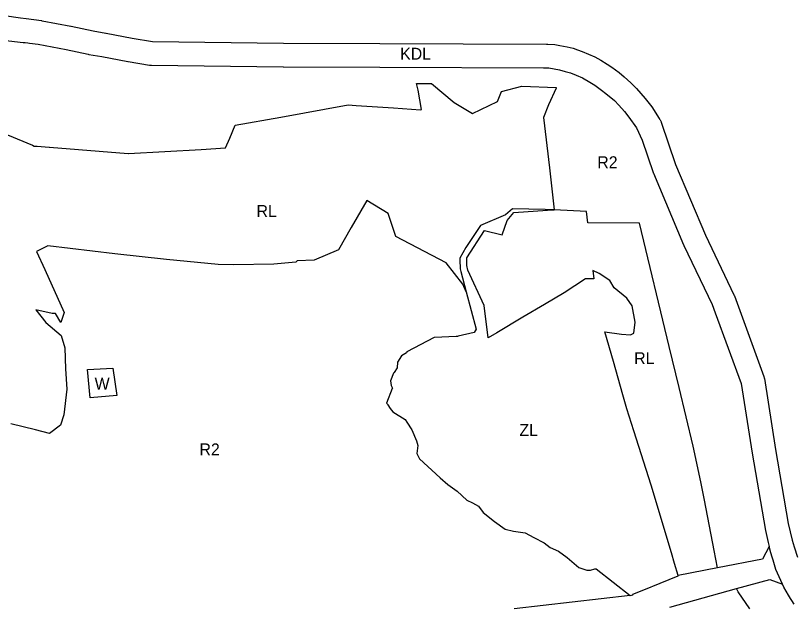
# Model space of a CAD drawing. Extents: x 7413438 to 7416393, y 5541665 to 5544118.
# Drawn here: x 7414455.4 to 7414848.9, y 5543282 to 5543578.9 of the extents above; entities that cross this region are included whole.
import ezdxf

# ---------------------------------------------------------------- set-up
doc = ezdxf.new("R2010")
doc.units = 0
doc.layers.add('linie_rozgraniczajace', color=7, linetype='Continuous')
doc.layers.add('oznaczenia_przeznaczen', color=7, linetype='Continuous')

msp = doc.modelspace()

# ---------------------------------------------------------------- linework, layer by layer
at = {"layer": 'linie_rozgraniczajace'}
for p, q in [((7414449.82, 5543578.9), (7414457.83, 5543577.78)), ((7414457.83, 5543577.78), (7414460.76, 5543577.39)), ((7414460.76, 5543577.39), (7414468.45, 5543576.35)), ((7414468.45, 5543576.35), (7414468.59, 5543576.33)), ((7414468.59, 5543576.33), (7414468.77, 5543576.3)), ((7414468.77, 5543576.3), (7414483.31, 5543573.58)), ((7414483.31, 5543573.58), (7414483.49, 5543573.54)), ((7414483.49, 5543573.54), (7414494.55, 5543571.12)), ((7414425.24, 5543568.95), (7414459.26, 5543565.39)), ((7414494.55, 5543571.12), (7414500.92, 5543570.09)), ((7414500.92, 5543570.09), (7414501.08, 5543570.06)), ((7414501.08, 5543570.06), (7414514.21, 5543567.57)), ((7414514.21, 5543567.57), (7414524.63, 5543565.84)), ((7414459.26, 5543565.39), (7414460.16, 5543565.34)), ((7414460.16, 5543565.34), (7414461.6, 5543565.15)), ((7414461.6, 5543565.15), (7414462.45, 5543565.04)), ((7414462.45, 5543565.04), (7414466.72, 5543564.48)), ((7414466.72, 5543564.48), (7414481.01, 5543561.8)), ((7414524.63, 5543565.84), (7414590.76, 5543564.98)), ((7414590.76, 5543564.98), (7414639.46, 5543564.84)), ((7414639.46, 5543564.84), (7414639.46, 5543564.84)), ((7414639.46, 5543564.84), (7414723.68, 5543564.55)), ((7414723.68, 5543564.55), (7414723.81, 5543564.54)), ((7414723.81, 5543564.54), (7414724.2, 5543564.52)), ((7414724.2, 5543564.52), (7414724.27, 5543564.51)), ((7414724.27, 5543564.51), (7414727.91, 5543564.31)), ((7414727.91, 5543564.31), (7414730.37, 5543563.77)), ((7414730.37, 5543563.77), (7414734.05, 5543563.08)), ((7414481.01, 5543561.8), (7414492.14, 5543559.36)), ((7414492.14, 5543559.36), (7414492.47, 5543559.3)), ((7414734.05, 5543563.08), (7414737.1, 5543562.37)), ((7414737.1, 5543562.37), (7414739.31, 5543561.63)), ((7414739.31, 5543561.63), (7414741.6, 5543560.76)), ((7414741.6, 5543560.76), (7414744.86, 5543559.48)), ((7414744.86, 5543559.48), (7414748, 5543558.06)), ((7414492.47, 5543559.3), (7414498.92, 5543558.26)), ((7414498.92, 5543558.26), (7414512.05, 5543555.76)), ((7414512.05, 5543555.76), (7414512.19, 5543555.74)), ((7414512.19, 5543555.74), (7414523.12, 5543553.93)), ((7414748, 5543558.06), (7414751.14, 5543556.39)), ((7414751.14, 5543556.39), (7414754.31, 5543554.34)), ((7414523.12, 5543553.93), (7414523.16, 5543553.92)), ((7414523.16, 5543553.92), (7414523.19, 5543553.92)), ((7414523.19, 5543553.92), (7414523.55, 5543553.87)), ((7414523.55, 5543553.87), (7414523.95, 5543553.85)), ((7414523.95, 5543553.85), (7414524.02, 5543553.85)), ((7414524.02, 5543553.85), (7414590.64, 5543552.98)), ((7414590.64, 5543552.98), (7414590.7, 5543552.98)), ((7414590.7, 5543552.98), (7414639.43, 5543552.84)), ((7414639.43, 5543552.84), (7414722.1, 5543552.55)), ((7414722.1, 5543552.55), (7414722.11, 5543552.55)), ((7414722.11, 5543552.55), (7414722.6, 5543552.55)), ((7414722.6, 5543552.55), (7414722.63, 5543552.54)), ((7414722.63, 5543552.54), (7414724.79, 5543552.5)), ((7414724.79, 5543552.5), (7414727.51, 5543551.97)), ((7414727.51, 5543551.97), (7414730.16, 5543551.56)), ((7414730.16, 5543551.56), (7414733.08, 5543550.72)), ((7414754.31, 5543554.34), (7414756.55, 5543552.89)), ((7414756.55, 5543552.89), (7414760.26, 5543550.09)), ((7414733.08, 5543550.72), (7414735.81, 5543549.93)), ((7414735.81, 5543549.93), (7414738.61, 5543548.82)), ((7414738.61, 5543548.82), (7414741.75, 5543547.41)), ((7414760.26, 5543550.09), (7414762.85, 5543547.94)), ((7414762.85, 5543547.94), (7414766.18, 5543545)), ((7414658.18, 5543543.92), (7414657.91, 5543544.56)), ((7414657.91, 5543544.56), (7414665.54, 5543544.53)), ((7414658.71, 5543541.16), (7414658.18, 5543543.92)), ((7414665.54, 5543544.53), (7414676.92, 5543534.99)), ((7414741.75, 5543547.41), (7414745.5, 5543545.31)), ((7414745.5, 5543545.31), (7414748.06, 5543543.75)), ((7414748.06, 5543543.75), (7414751.44, 5543541.25)), ((7414766.18, 5543545), (7414769.12, 5543542.1)), ((7414660.52, 5543531.53), (7414658.71, 5543541.16)), ((7414698.91, 5543535.45), (7414700.84, 5543540.53)), ((7414700.84, 5543540.53), (7414711.16, 5543543.24)), ((7414711.16, 5543543.24), (7414728.58, 5543542.52)), ((7414728.53, 5543542.16), (7414724.56, 5543533.83)), ((7414728.58, 5543542.52), (7414728.53, 5543542.16)), ((7414751.44, 5543541.25), (7414753.56, 5543539.61)), ((7414769.12, 5543542.1), (7414773.44, 5543536.95)), ((7414753.56, 5543539.61), (7414757.94, 5543536)), ((7414757.94, 5543536), (7414760.22, 5543533.59)), ((7414773.44, 5543536.95), (7414776.88, 5543532.79)), ((7414589.39, 5543527.67), (7414623.38, 5543533.78)), ((7414623.38, 5543533.78), (7414627.44, 5543533.51)), ((7414627.44, 5543533.51), (7414646.34, 5543532.24)), ((7414646.34, 5543532.24), (7414659.92, 5543531.33)), ((7414676.92, 5543534.99), (7414686.15, 5543529.51)), ((7414686.15, 5543529.51), (7414698.91, 5543535.45)), ((7414724.56, 5543533.83), (7414722.08, 5543527.36)), ((7414760.22, 5543533.59), (7414762.98, 5543530.49)), ((7414776.88, 5543532.79), (7414780.59, 5543526.86)), ((7414659.92, 5543531.33), (7414660.52, 5543531.53)), ((7414762.98, 5543530.49), (7414765.28, 5543527.63)), ((7414566.41, 5543523.54), (7414589.39, 5543527.67)), ((7414722.08, 5543527.36), (7414725.09, 5543502)), ((7414765.28, 5543527.63), (7414769.14, 5543522.19)), ((7414780.59, 5543526.86), (7414780.64, 5543526.8)), ((7414780.64, 5543526.8), (7414780.79, 5543526.6)), ((7414780.79, 5543526.6), (7414781.01, 5543526.28)), ((7414781.01, 5543526.28), (7414781.21, 5543525.94)), ((7414781.21, 5543525.94), (7414781.38, 5543525.59)), ((7414781.38, 5543525.59), (7414781.54, 5543525.23)), ((7414781.54, 5543525.23), (7414781.62, 5543524.99)), ((7414781.62, 5543524.99), (7414788.78, 5543503.77)), ((7414563.55, 5543516.96), (7414566.41, 5543523.54)), ((7414769.14, 5543522.19), (7414772.02, 5543515.92)), ((7414451.36, 5543518.66), (7414463.89, 5543513.39)), ((7414561.39, 5543512.03), (7414563.55, 5543516.96)), ((7414463.89, 5543513.39), (7414464.79, 5543513.01)), ((7414464.79, 5543513.01), (7414466.24, 5543512.9)), ((7414466.24, 5543512.9), (7414472.32, 5543512.41)), ((7414472.32, 5543512.41), (7414472.58, 5543512.39)), ((7414472.58, 5543512.39), (7414512.33, 5543509.21)), ((7414772.02, 5543515.92), (7414777.48, 5543499.73)), ((7414512.33, 5543509.21), (7414512.41, 5543509.2)), ((7414512.41, 5543509.2), (7414549.07, 5543511.32)), ((7414549.07, 5543511.32), (7414561.39, 5543512.03)), ((7414725.09, 5543502), (7414727.48, 5543480.86)), ((7414788.78, 5543503.77), (7414803.87, 5543467.92)), ((7414777.48, 5543499.73), (7414777.56, 5543499.49)), ((7414777.56, 5543499.49), (7414777.63, 5543499.32)), ((7414777.63, 5543499.32), (7414792.87, 5543463.13)), ((7414632.89, 5543485.46), (7414625, 5543471.83)), ((7414643.7, 5543479.01), (7414632.89, 5543485.46)), ((7414706.45, 5543481.38), (7414702.82, 5543478.25)), ((7414723.01, 5543480.97), (7414706.45, 5543481.38)), ((7414727.48, 5543480.86), (7414723.01, 5543480.97)), ((7414724.04, 5543480.62), (7414727.48, 5543480.86)), ((7414743.75, 5543479.89), (7414727.48, 5543480.86)), ((7414647.46, 5543467.36), (7414643.7, 5543479.01)), ((7414702.82, 5543478.25), (7414690.34, 5543472.8)), ((7414703.79, 5543475.36), (7414707.18, 5543479.43)), ((7414707.18, 5543479.43), (7414724.04, 5543480.62)), ((7414744.47, 5543474.26), (7414743.75, 5543479.89)), ((7414690.34, 5543472.8), (7414682.82, 5543461.74)), ((7414701.15, 5543468.2), (7414703.79, 5543475.36)), ((7414770.58, 5543474.13), (7414744.47, 5543474.26)), ((7414785.56, 5543411.81), (7414770.58, 5543474.13)), ((7414625, 5543471.83), (7414618.54, 5543460.64)), ((7414683.33, 5543456.51), (7414692.25, 5543470.39)), ((7414692.25, 5543470.39), (7414701.15, 5543468.2)), ((7414672.96, 5543454.07), (7414647.46, 5543467.36)), ((7414803.87, 5543467.92), (7414818.27, 5543437.93)), ((7414471.72, 5543462.53), (7414466.03, 5543459.67)), ((7414505.47, 5543458.65), (7414471.72, 5543462.53)), ((7414682.82, 5543461.74), (7414679.75, 5543456.32)), ((7414792.87, 5543463.13), (7414792.96, 5543462.94)), ((7414792.96, 5543462.94), (7414792.99, 5543462.86)), ((7414792.99, 5543462.86), (7414807.33, 5543433)), ((7414466.03, 5543459.67), (7414470.1, 5543450.65)), ((7414531.7, 5543455.77), (7414505.47, 5543458.65)), ((7414618.54, 5543460.64), (7414606.28, 5543455.3)), ((7414557.79, 5543453.24), (7414531.7, 5543455.77)), ((7414565.47, 5543453.08), (7414557.79, 5543453.24)), ((7414585.8, 5543453.35), (7414565.47, 5543453.08)), ((7414596.91, 5543454.41), (7414585.8, 5543453.35)), ((7414597.69, 5543455.08), (7414596.91, 5543454.41)), ((7414606.28, 5543455.3), (7414597.69, 5543455.08)), ((7414681.33, 5543443.17), (7414672.96, 5543454.07)), ((7414679.75, 5543456.32), (7414679.81, 5543455.56)), ((7414679.81, 5543455.56), (7414679.93, 5543451.07)), ((7414683.36, 5543452.73), (7414683.33, 5543456.51)), ((7414470.1, 5543450.65), (7414479.91, 5543428.89)), ((7414679.93, 5543451.07), (7414680.32, 5543449.59)), ((7414680.32, 5543449.59), (7414683.02, 5543439.44)), ((7414683.94, 5543450.29), (7414683.36, 5543452.73)), ((7414692.07, 5543432.48), (7414683.94, 5543450.29)), ((7414747.1, 5543450.22), (7414747.07, 5543450.17)), ((7414747.07, 5543450.17), (7414747.52, 5543445.95)), ((7414750.24, 5543448.56), (7414747.1, 5543450.22)), ((7414743.4, 5543446.01), (7414732.49, 5543438.88)), ((7414747.52, 5543445.95), (7414743.4, 5543446.01)), ((7414755.65, 5543445.12), (7414750.24, 5543448.56)), ((7414683, 5543439.43), (7414681.33, 5543443.17)), ((7414757.73, 5543441.45), (7414755.65, 5543445.12)), ((7414764.18, 5543436.23), (7414757.73, 5543441.45)), ((7414683.02, 5543439.44), (7414683, 5543439.43)), ((7414683, 5543439.43), (7414683.04, 5543439.35)), ((7414683.04, 5543439.35), (7414688.07, 5543420.51)), ((7414732.49, 5543438.88), (7414722.55, 5543432.98)), ((7414818.27, 5543437.93), (7414818.31, 5543437.85)), ((7414818.31, 5543437.85), (7414818.46, 5543437.49)), ((7414818.46, 5543437.49), (7414818.5, 5543437.39)), ((7414818.5, 5543437.39), (7414818.54, 5543437.29)), ((7414766.92, 5543432.25), (7414764.18, 5543436.23)), ((7414818.54, 5543437.29), (7414833.39, 5543396.69)), ((7414473.79, 5543428.36), (7414465.7, 5543430.34)), ((7414465.7, 5543430.34), (7414470.72, 5543423.93)), ((7414694.23, 5543416.15), (7414692.07, 5543432.48)), ((7414722.55, 5543432.98), (7414711.68, 5543426.52)), ((7414768.43, 5543424.04), (7414766.92, 5543432.25)), ((7414807.33, 5543433), (7414808.88, 5543428.75)), ((7414475.54, 5543428.51), (7414473.79, 5543428.36)), ((7414478.17, 5543423.91), (7414475.54, 5543428.51)), ((7414479.91, 5543428.89), (7414478.17, 5543423.91)), ((7414711.68, 5543426.52), (7414698.47, 5543418.67)), ((7414808.88, 5543428.75), (7414821.92, 5543393.11)), ((7414470.72, 5543423.93), (7414478.4, 5543417.36)), ((7414767.69, 5543418.42), (7414768.43, 5543424.04)), ((7414687.08, 5543418.85), (7414678.91, 5543416.94)), ((7414688.07, 5543420.51), (7414687.08, 5543418.85)), ((7414698.47, 5543418.67), (7414694.23, 5543416.15)), ((7414757.41, 5543404.25), (7414753.15, 5543419.23)), ((7414753.15, 5543419.23), (7414761.59, 5543417.96)), ((7414761.59, 5543417.96), (7414766.01, 5543417.6)), ((7414766.01, 5543417.6), (7414767.69, 5543418.42)), ((7414478.4, 5543417.36), (7414480.24, 5543411.08)), ((7414666.9, 5543416.39), (7414653.04, 5543409.02)), ((7414667.06, 5543416.39), (7414666.9, 5543416.39)), ((7414678.02, 5543416.74), (7414667.06, 5543416.39)), ((7414678.6, 5543416.75), (7414678.02, 5543416.74)), ((7414678.91, 5543416.94), (7414678.6, 5543416.75)), ((7414480.24, 5543411.08), (7414480.67, 5543400.51)), ((7414790.57, 5543391.01), (7414785.56, 5543411.81)), ((7414650.42, 5543407.12), (7414648.28, 5543403.82)), ((7414652.85, 5543408.62), (7414650.42, 5543407.12)), ((7414652.88, 5543408.63), (7414652.85, 5543408.62)), ((7414652.89, 5543408.64), (7414652.88, 5543408.63)), ((7414653.04, 5543409.02), (7414652.89, 5543408.64)), ((7414648.28, 5543403.82), (7414648.15, 5543401.02)), ((7414762.17, 5543387.42), (7414757.41, 5543404.25)), ((7414480.67, 5543400.51), (7414481.36, 5543390.21)), ((7414491.67, 5543400.15), (7414504.59, 5543400.9)), ((7414493, 5543385.87), (7414491.67, 5543400.15)), ((7414504.59, 5543400.9), (7414506.48, 5543387.01)), ((7414646.28, 5543398.33), (7414644.85, 5543394.46)), ((7414646.65, 5543398.6), (7414646.28, 5543398.33)), ((7414648.15, 5543401.02), (7414646.65, 5543398.6)), ((7414644.85, 5543394.46), (7414645.16, 5543392.01)), ((7414833.39, 5543396.69), (7414833.48, 5543396.42)), ((7414833.48, 5543396.42), (7414833.59, 5543396.04)), ((7414833.59, 5543396.04), (7414833.67, 5543395.65)), ((7414833.67, 5543395.65), (7414833.68, 5543395.57)), ((7414833.68, 5543395.57), (7414839.36, 5543359.82)), ((7414481.36, 5543390.21), (7414479.77, 5543377.17)), ((7414645.7, 5543390.5), (7414642.75, 5543383.06)), ((7414645.16, 5543392.01), (7414645.79, 5543390.73)), ((7414645.79, 5543390.73), (7414645.7, 5543390.5)), ((7414797.69, 5543361.43), (7414790.57, 5543391.01)), ((7414821.92, 5543393.11), (7414827.52, 5543357.91)), ((7414506.48, 5543387.01), (7414493, 5543385.87)), ((7414764.19, 5543380.28), (7414762.17, 5543387.42)), ((7414642.75, 5543383.06), (7414643.54, 5543382.43)), ((7414643.54, 5543382.43), (7414643.51, 5543382.37)), ((7414643.51, 5543382.37), (7414644.67, 5543380.38)), ((7414644.67, 5543380.38), (7414646.02, 5543378.82)), ((7414646.02, 5543378.82), (7414652.2, 5543374.83)), ((7414767.75, 5543369.25), (7414764.19, 5543380.28)), ((7414479.77, 5543377.17), (7414478.12, 5543372.07)), ((7414652.2, 5543374.83), (7414653.12, 5543373.47)), ((7414465.51, 5543369.7), (7414452.94, 5543372.64)), ((7414478.12, 5543372.07), (7414472.47, 5543367.87)), ((7414653.12, 5543373.47), (7414655.64, 5543369.59)), ((7414472.47, 5543367.87), (7414465.51, 5543369.7)), ((7414655.64, 5543369.59), (7414658.01, 5543364.1)), ((7414776.5, 5543341.71), (7414767.75, 5543369.25)), ((7414658.01, 5543364.1), (7414658.53, 5543361.75)), ((7414658.53, 5543361.75), (7414658.16, 5543357.76)), ((7414801.65, 5543343.35), (7414797.69, 5543361.43)), ((7414839.36, 5543359.82), (7414845.78, 5543322.35)), ((7414658.16, 5543357.76), (7414659.45, 5543355.02)), ((7414659.45, 5543355.02), (7414669.84, 5543345.5)), ((7414827.52, 5543357.91), (7414827.53, 5543357.84)), ((7414827.53, 5543357.84), (7414834.2, 5543318.86)), ((7414669.84, 5543345.5), (7414673.74, 5543342)), ((7414803.42, 5543334.22), (7414801.65, 5543343.35)), ((7414673.74, 5543342), (7414678.49, 5543338.76)), ((7414786.81, 5543307.58), (7414776.5, 5543341.71)), ((7414678.49, 5543338.76), (7414683.3, 5543334.12)), ((7414683.3, 5543334.12), (7414686.26, 5543332.84)), ((7414686.26, 5543332.84), (7414689.23, 5543331.13)), ((7414689.23, 5543331.13), (7414691.62, 5543327.9)), ((7414808.36, 5543308.71), (7414803.42, 5543334.22)), ((7414691.62, 5543327.9), (7414697.28, 5543323.4)), ((7414697.28, 5543323.4), (7414702.7, 5543319.53)), ((7414702.7, 5543319.53), (7414706.94, 5543318.52)), ((7414845.78, 5543322.35), (7414847.8, 5543313.89)), ((7414706.94, 5543318.52), (7414712.88, 5543317.69)), ((7414712.88, 5543317.69), (7414717.28, 5543315.29)), ((7414834.2, 5543318.86), (7414835.66, 5543312.81)), ((7414717.28, 5543315.29), (7414722.44, 5543312.54)), ((7414722.44, 5543312.54), (7414725.55, 5543310.2)), ((7414835.66, 5543312.81), (7414836.1, 5543310.83)), ((7414847.8, 5543313.89), (7414848.7, 5543310.57)), ((7414725.55, 5543310.2), (7414729.7, 5543308.43)), ((7414729.7, 5543308.43), (7414734.02, 5543305.27)), ((7414788.32, 5543302.16), (7414786.81, 5543307.58)), ((7414810.06, 5543299.94), (7414808.36, 5543308.71)), ((7414836.1, 5543310.83), (7414832.72, 5543304.42)), ((7414836.93, 5543307.63), (7414836.1, 5543310.83)), ((7414837.63, 5543305.38), (7414836.93, 5543307.63)), ((7414848.7, 5543310.57), (7414850.38, 5543305.35)), ((7414734.02, 5543305.27), (7414740.03, 5543300.14)), ((7414832.72, 5543304.42), (7414810.06, 5543299.94)), ((7414837.78, 5543304.89), (7414837.63, 5543305.38)), ((7414838.08, 5543303.91), (7414837.78, 5543304.89)), ((7414839.51, 5543299.2), (7414838.08, 5543303.91)), ((7414740.03, 5543300.14), (7414743.96, 5543298.8)), ((7414790.21, 5543296.03), (7414788.32, 5543302.16)), ((7414810.06, 5543299.94), (7414790.21, 5543296.03)), ((7414743.96, 5543298.8), (7414745.78, 5543298.87)), ((7414745.78, 5543298.87), (7414748.02, 5543299.39)), ((7414748.02, 5543299.39), (7414748.72, 5543299.42)), ((7414748.72, 5543299.42), (7414765.82, 5543285.93)), ((7414789.93, 5543295.83), (7414780.94, 5543292.14)), ((7414790.21, 5543296.03), (7414789.93, 5543295.83)), ((7414841.23, 5543295.43), (7414839.51, 5543299.2)), ((7414780.94, 5543292.14), (7414772.69, 5543288.75)), ((7414819.64, 5543289.46), (7414836.41, 5543294.1)), ((7414836.41, 5543294.1), (7414842.93, 5543291.69)), ((7414842.93, 5543291.69), (7414841.23, 5543295.43)), ((7414772.69, 5543288.75), (7414767.11, 5543286.46)), ((7414785.95, 5543280.15), (7414819.64, 5543289.46)), ((7414820.45, 5543287.85), (7414819.64, 5543289.46)), ((7414826.4, 5543279.18), (7414820.45, 5543287.85)), ((7414843.6, 5543290.23), (7414842.93, 5543291.69)), ((7414845.87, 5543286.19), (7414843.6, 5543290.23)), ((7414765.82, 5543285.93), (7414707.33, 5543279.31)), ((7414765.95, 5543285.83), (7414765.82, 5543285.93)), ((7414767.08, 5543286.19), (7414765.95, 5543285.83)), ((7414765.95, 5543285.83), (7414765.95, 5543285.83)), ((7414767.11, 5543286.46), (7414767.08, 5543286.23)), ((7414767.08, 5543286.23), (7414767.08, 5543286.19)), ((7414846.03, 5543285.92), (7414845.87, 5543286.19)), ((7414846.08, 5543285.85), (7414846.03, 5543285.92)), ((7414848.81, 5543281.67), (7414846.08, 5543285.85))]:
    msp.add_line(p, q, dxfattribs=at)

# ---------------------------------------------------------------- texts
at = {"layer": 'oznaczenia_przeznaczen'}
for s, p in [('KDL', (7414649.67, 5543556.64)), ('R2', (7414749.28, 5543501.83)), ('RL', (7414577.1, 5543477.21)), ('RL', (7414767.91, 5543402.86)), ('W', (7414495.33, 5543389.96)), ('ZL', (7414709.92, 5543366.57)), ('R2', (7414548.29, 5543356.79))]:
    msp.add_text(s, height=6, dxfattribs=at).set_placement(p)

doc.saveas('drawing.dxf')
